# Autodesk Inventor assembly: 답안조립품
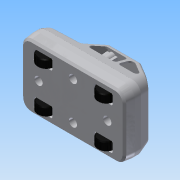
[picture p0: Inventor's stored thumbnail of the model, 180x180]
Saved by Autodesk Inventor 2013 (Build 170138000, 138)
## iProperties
Created: 2015-05
Part Number: 답안조립품
Document SubType Name: Assembly
Designer: Administrator
Author: Administrator
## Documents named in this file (7)
- C:\Documents and Settings\Administrator\바탕 화면\450507V1018\답안조립품.iam
- C:\Documents and Settings\Administrator\바탕 화면\450507V1018\1-본체.ipt
- C:\Documents and Settings\Administrator\바탕 화면\450507V1018\커버.ipt
- C:\Documents and Settings\Administrator\바탕 화면\450507V1018\바퀴.ipt
- C:\Documents and Settings\Administrator\바탕 화면\450507V1018\바퀴고정부.ipt
- C:\Documents and Settings\Administrator\바탕 화면\450507V1018\M2x4.ipt
- C:\Documents and Settings\Administrator\바탕 화면\450507V1018\M4x10.ipt
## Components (21 placed, 3 different names)
1. 1-본체:1
2. M2x4:1
3. M2x4:2
4. M2x4:3
5. M2x4:4
6. M2x4:5
7. M2x4:6
8. M2x4:7
9. M2x4:8
10. M2x4:9
11. M2x4:10
12. M2x4:11
13. M2x4:12
14. M2x4:13
15. M2x4:14
16. M2x4:15
17. M2x4:16
18. M4x10:1
19. M4x10:2
20. M4x10:3
21. M4x10:4
